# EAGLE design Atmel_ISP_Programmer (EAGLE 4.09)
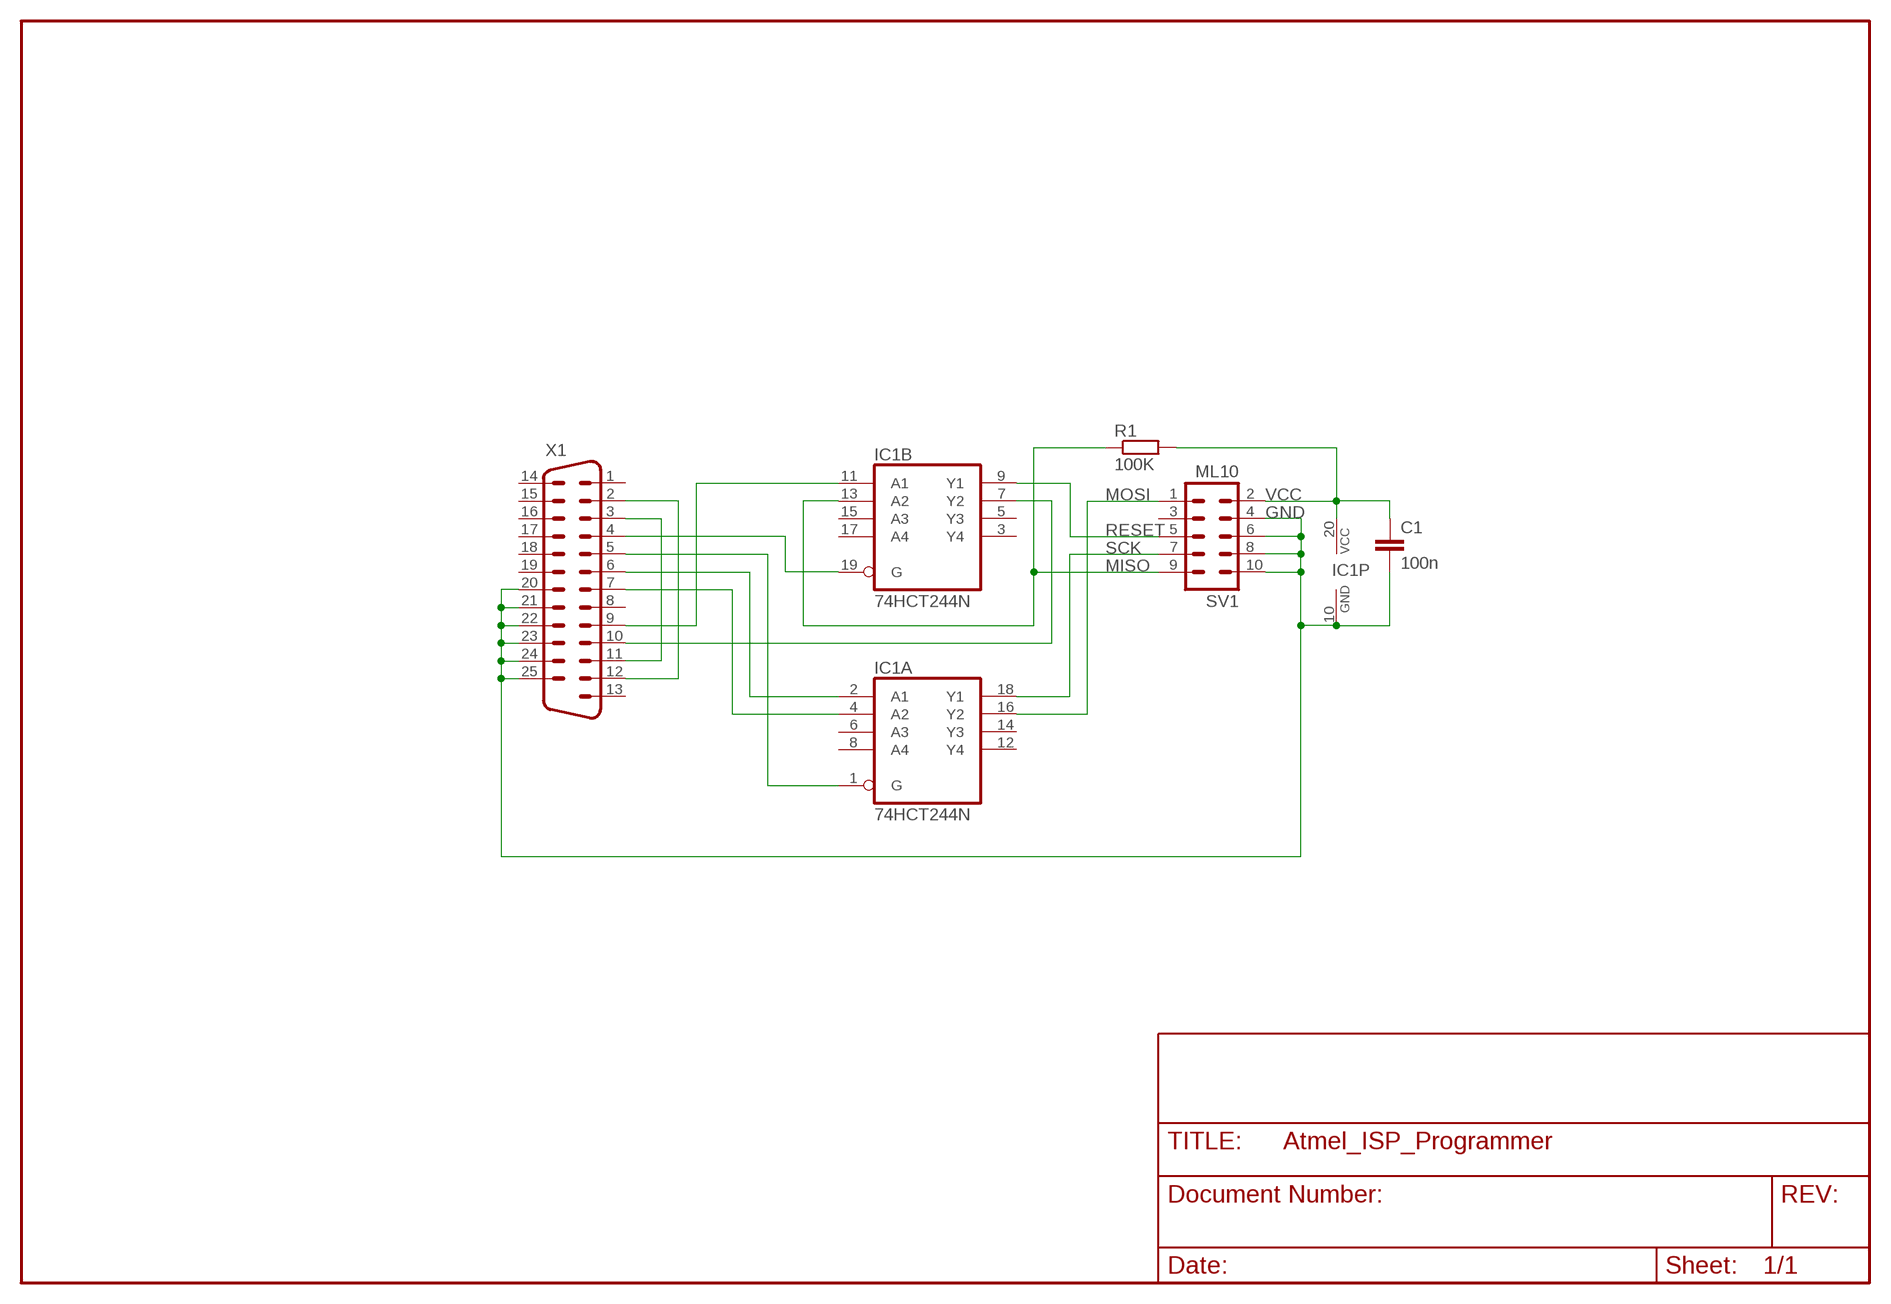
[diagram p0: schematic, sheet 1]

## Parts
C1  100n  C-EU025-025X050  [C025-025X050]
IC1  74HCT244N  [DIL20]
R1  100K  R-EU_0207/10  [0207/10]
SV1  ML10  [ML10]
X1  M25HP  [M25HP]

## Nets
GND: C1.2 IC1.10(P:GND) SV1.4 SV1.6 SV1.8 SV1.10 X1.20 X1.21 X1.22 X1.23 X1.24 X1.25
MISO: IC1.13(B:A2) R1.1 SV1.9
MOSI: IC1.16(A:Y2) SV1.1
N$1: X1.2 X1.12
N$2: X1.3 X1.11
N$3: IC1.19(B:G) X1.4
N$5: IC1.1(A:G) X1.5
N$6: IC1.2(A:A1) X1.6
N$7: IC1.4(A:A2) X1.7
N$8: IC1.11(B:A1) X1.9
N$9: IC1.7(B:Y2) X1.10
RESET: IC1.9(B:Y1) SV1.5
SCK: IC1.18(A:Y1) SV1.7
VCC: C1.1 IC1.20(P:VCC) R1.2 SV1.2
Unconnected: IC1.3(B:Y4) IC1.5(B:Y3) IC1.6(A:A3) IC1.8(A:A4) IC1.12(A:Y4) IC1.14(A:Y3) IC1.15(B:A3) IC1.17(B:A4) SV1.3 X1.1 X1.8 X1.13 X1.14 X1.15 X1.16 X1.17 X1.18 X1.19

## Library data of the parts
C1 = rcl:C-EU: CAPACITOR, European symbol
IC1 = 74xx-eu:74*244: Octal BUFFER and LINE DRIVER, 3-state
R1 = rcl:R-EU_: RESISTOR, European symbol
SV1 = CON-ML:ML10
X1 = con-subd:M25: SUB-D

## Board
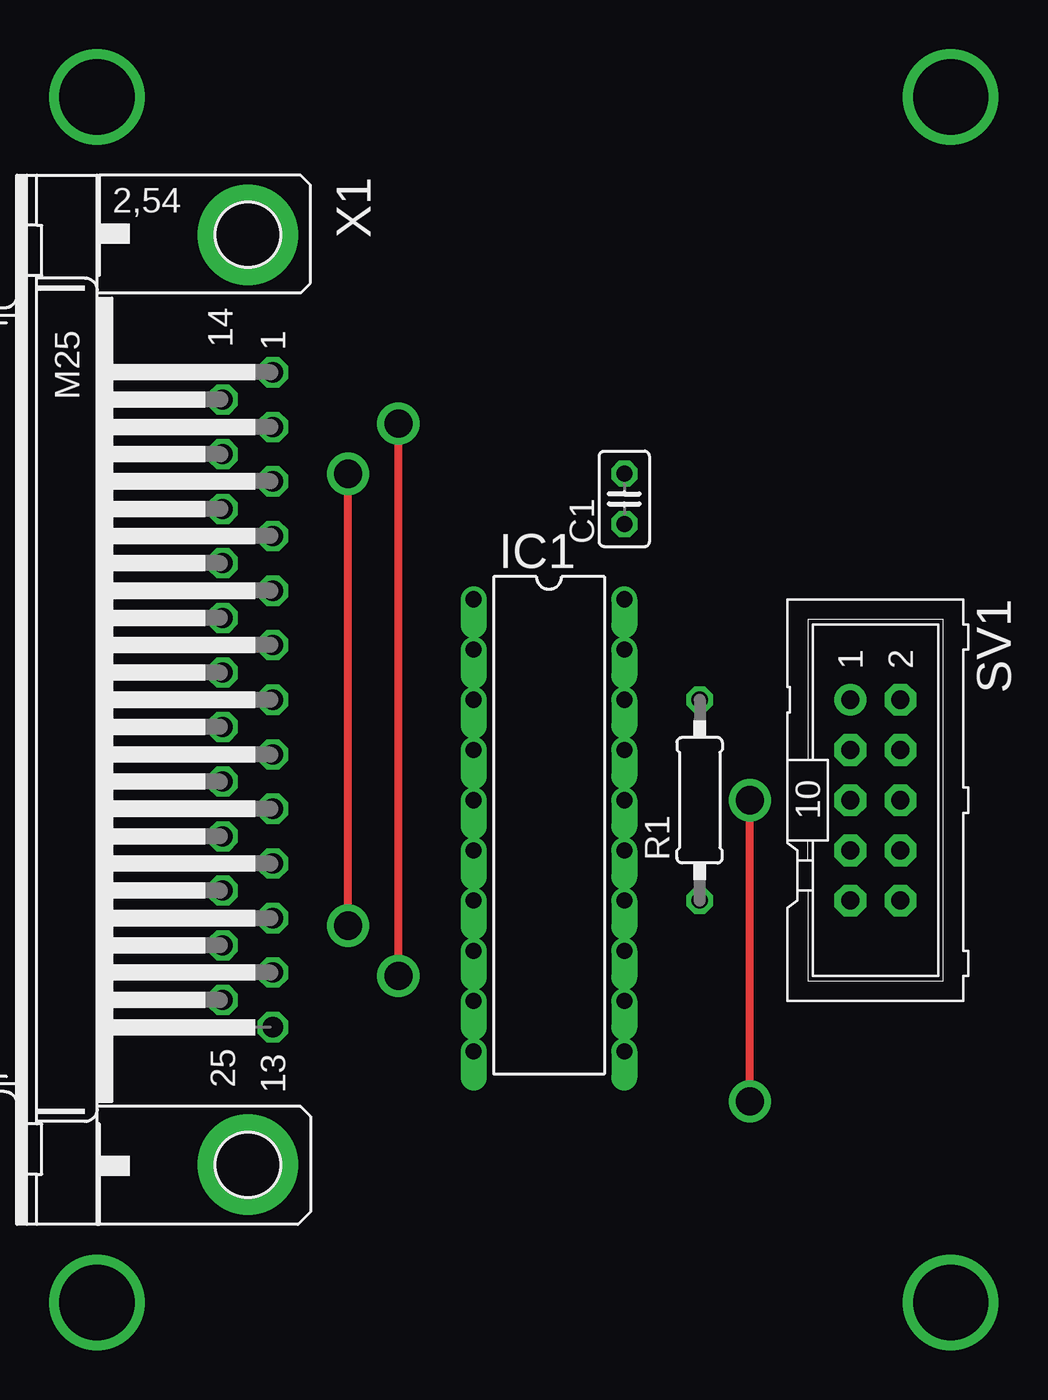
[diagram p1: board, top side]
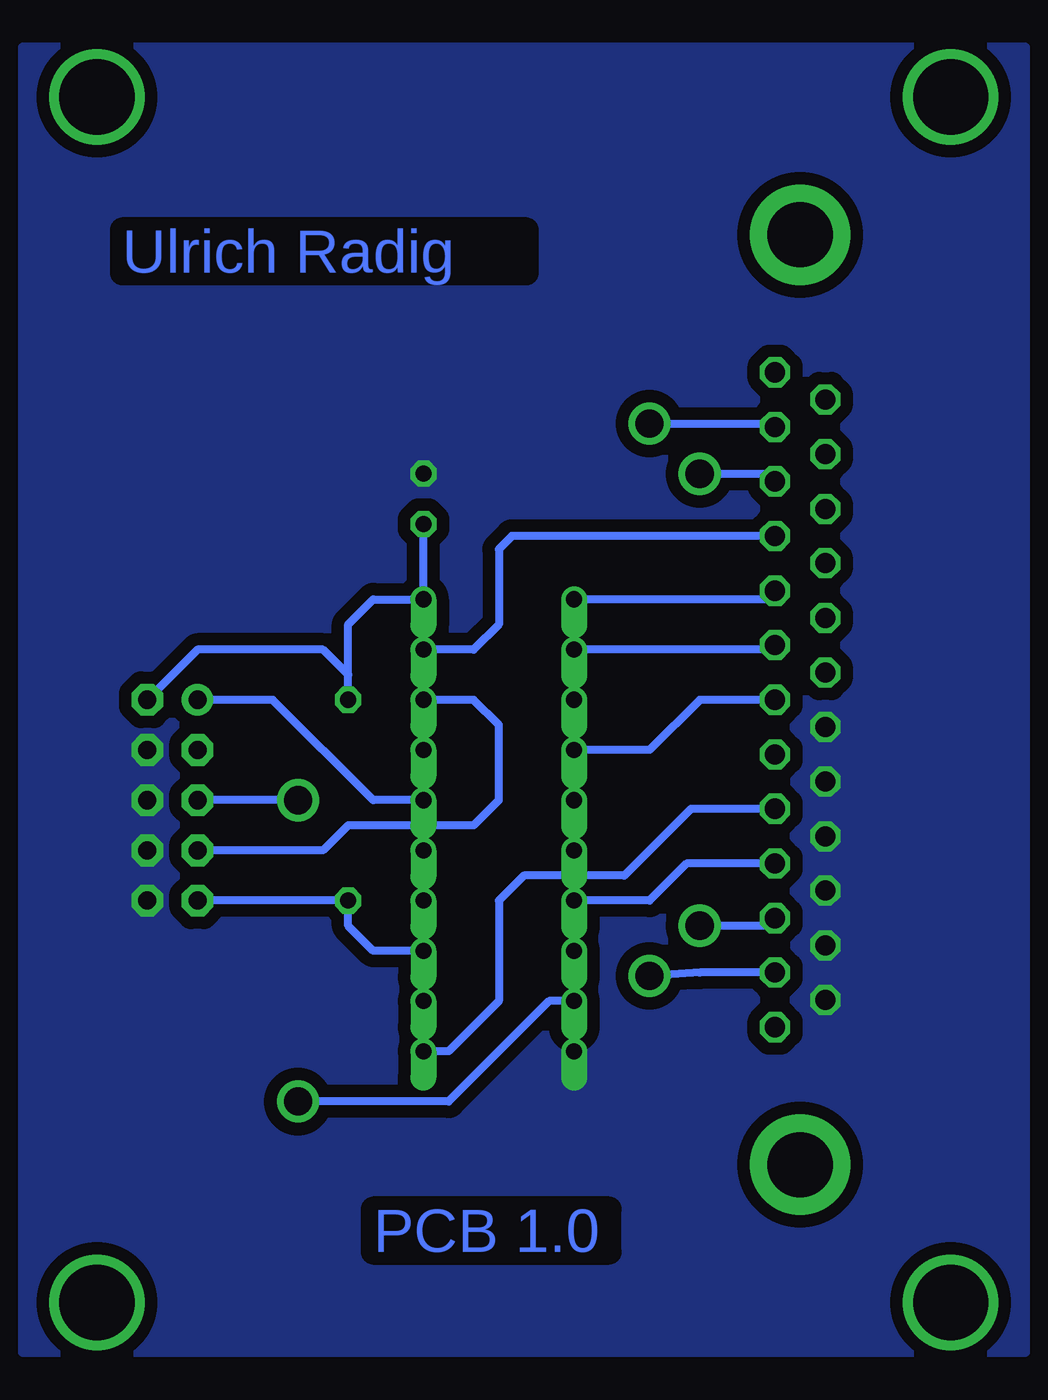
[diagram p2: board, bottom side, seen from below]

No outline drawn. Coordinates in mm, seen from the top.
Copper layers used: Top, Bottom

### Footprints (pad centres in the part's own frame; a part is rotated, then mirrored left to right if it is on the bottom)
C025-025X050 = drill 0.813 octagon: 1 -1.27,0; 2 1.27,0
DIL20 = drill 0.813 offset: 1 -11.43,-3.81; 2 -8.89,-3.81; 3 -6.35,-3.81; 4 -3.81,-3.81; 5 -1.27,-3.81; 6 1.27,-3.81; 7 3.81,-3.81; 8 6.35,-3.81; 9 8.89,-3.81; 10 11.43,-3.81; 11 11.43,3.81; 12 8.89,3.81; 13 6.35,3.81; 14 3.81,3.81; 15 1.27,3.81; 16 -1.27,3.81; 17 -3.81,3.81; 18 -6.35,3.81; 19 -8.89,3.81; 20 -11.43,3.81
0207/10 = drill 0.813 octagon: 1 -5.08,0; 2 5.08,0
ML10 = drill 0.914 pad 1.6 round: 1 -5.08,-1.27 | drill 0.914 pad 1.6 octagon: 2 -5.08,1.27; 3 -2.54,-1.27; 4 -2.54,1.27; 5 0,-1.27; 6 0,1.27; 7 2.54,-1.27; 8 2.54,1.27; 9 5.08,-1.27; 10 5.08,1.27
M25HP = drill 1.016 octagon: 1 -16.561,1.27; 2 -13.792,1.27; 3 -11.049,1.27; 4 -8.28,1.27; 5 -5.512,1.27; 6 -2.769,1.27; 7 0,1.27; 8 2.769,1.27; 9 5.512,1.27; 10 8.28,1.27; 11 11.049,1.27; 12 13.792,1.27; 13 16.561,1.27; 14 -15.189,-1.27; 15 -12.421,-1.27; 16 -9.652,-1.27; 17 -6.909,-1.27; 18 -4.14,-1.27; 19 -1.372,-1.27; 20 1.372,-1.27; 21 4.14,-1.27; 22 6.909,-1.27; 23 9.652,-1.27; 24 12.421,-1.27; 25 15.189,-1.27 | drill 3.302 pad 5.08 round: G1 -23.52,0; G2 23.52,0

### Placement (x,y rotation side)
C1  30.48,44.45 90 top
IC1  26.67,27.94 270 top
R1  34.29,29.21 90 top
SV1  43.18,29.21 270 top
X1  11.43,34.29 270 top

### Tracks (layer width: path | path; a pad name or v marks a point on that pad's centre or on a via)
GND
  pour Bottom (isolate 0.635, no thermals): 0,1.27 0,67.31 50.8,67.31 50.8,1.27
MISO
  Bottom 0.406: IC1.13 33.02,21.59 34.29,22.86 R1.1 SV1.9
MOSI
  Bottom 0.406: IC1.16 33.02,29.21 38.1,34.29 SV1.1
N$1  (via drill 1.42)
  Top 0.406: v19.05,20.32 v19.05,48.26
  Bottom 0.406: X1.12 16.51,20.5 v19.05,20.32 | X1.2 12.7,48.26 v19.05,48.26
N$2  (via drill 1.42)
  Top 0.406: v16.51,22.86 v16.51,45.72
  Bottom 0.406: X1.3 13.08,45.72 v16.51,45.72 | X1.11 13.08,22.86 v16.51,22.86
N$3
  Bottom 0.406: X1.4 26.01,42.57 26.67,41.91 26.67,38.1 27.94,36.83 IC1.19
N$4  (via drill 3.81)
  other vias: 3.81,3.81
N$5
  Bottom 0.406: X1.5 13.13,39.37 IC1.1
N$6
  Bottom 0.406: X1.6 12.93,36.83 IC1.2
N$7
  Bottom 0.406: X1.7 16.51,34.29 19.05,31.75 IC1.4
N$8
  Bottom 0.406: X1.9 16.94,28.78 20.32,25.4 25.4,25.4 26.67,24.13 26.67,19.05 29.21,16.51 IC1.11
N$9
  Bottom 0.406: X1.10 17.17,26.01 19.05,24.13 IC1.7
N$10  (via drill 3.81)
  other vias: 46.99,3.81
N$11  (via drill 3.81)
  other vias: 46.99,64.77
N$12  (via drill 3.81)
  other vias: 3.81,64.77
RESET  (via drill 1.42)
  Top 0.406: v36.83,13.97 v36.83,29.21
  Bottom 0.406: v36.83,29.21 SV1.5 | IC1.9 24.13,19.05 29.21,13.97 v36.83,13.97
SCK
  Bottom 0.406: IC1.18 27.94,34.29 26.67,33.02 26.67,29.21 27.94,27.94 34.29,27.94 35.56,26.67 SV1.7
VCC
  Bottom 0.406: C1.1 IC1.20 33.02,39.37 34.29,38.1 R1.2 34.29,35.56 35.56,36.83 41.91,36.83 SV1.2

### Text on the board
Bottom: Ulrich Radig | PCB 1.0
